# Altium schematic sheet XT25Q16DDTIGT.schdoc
size 127 x 101 mm
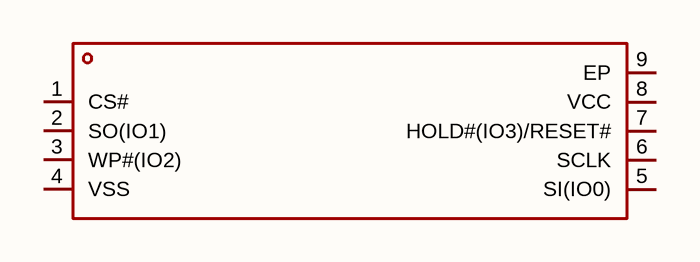
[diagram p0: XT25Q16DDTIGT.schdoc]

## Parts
U?  xt25q16ddtigt  [USON8_L3.0-W2.0-P0.50-TL-EP-1]  (value not drawn)

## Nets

Not connected (* = marked no-connect by the designer): U? 1(CS#) 2(SO(IO1)) 3(WP#(IO2)) 4(VSS) 5(SI(IO0)) 6(SCLK) 7(HOLD#(IO3)/RESET#) 8(VCC) 9(EP)

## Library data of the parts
U? = xt25q16ddtigt: 接口类型:SPI;存储容量:16Mbit;时钟频率(fc):108MHz;; Manufacturer: XTX(芯天下); AddInBom: yes; ModelId: 76b4d0649e1a481e9ffb1ca37c19be3a; ModelTransform: 118.8974,79.527,0,0,0,0,0,0,0; Interface: SPI; Memory Size: 16Mbit; Clock Frequency: 108MHz; Voltage - Supply: 1.65V~2.1V; Standby Supply Current: 0.3uA; Program / Erase Cycles: 100000次; Page Programming Time (Tpp): 350us; Block Erase Time(tBE): 150ms@(64KB); Data Retention - TDR (Year): 20年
